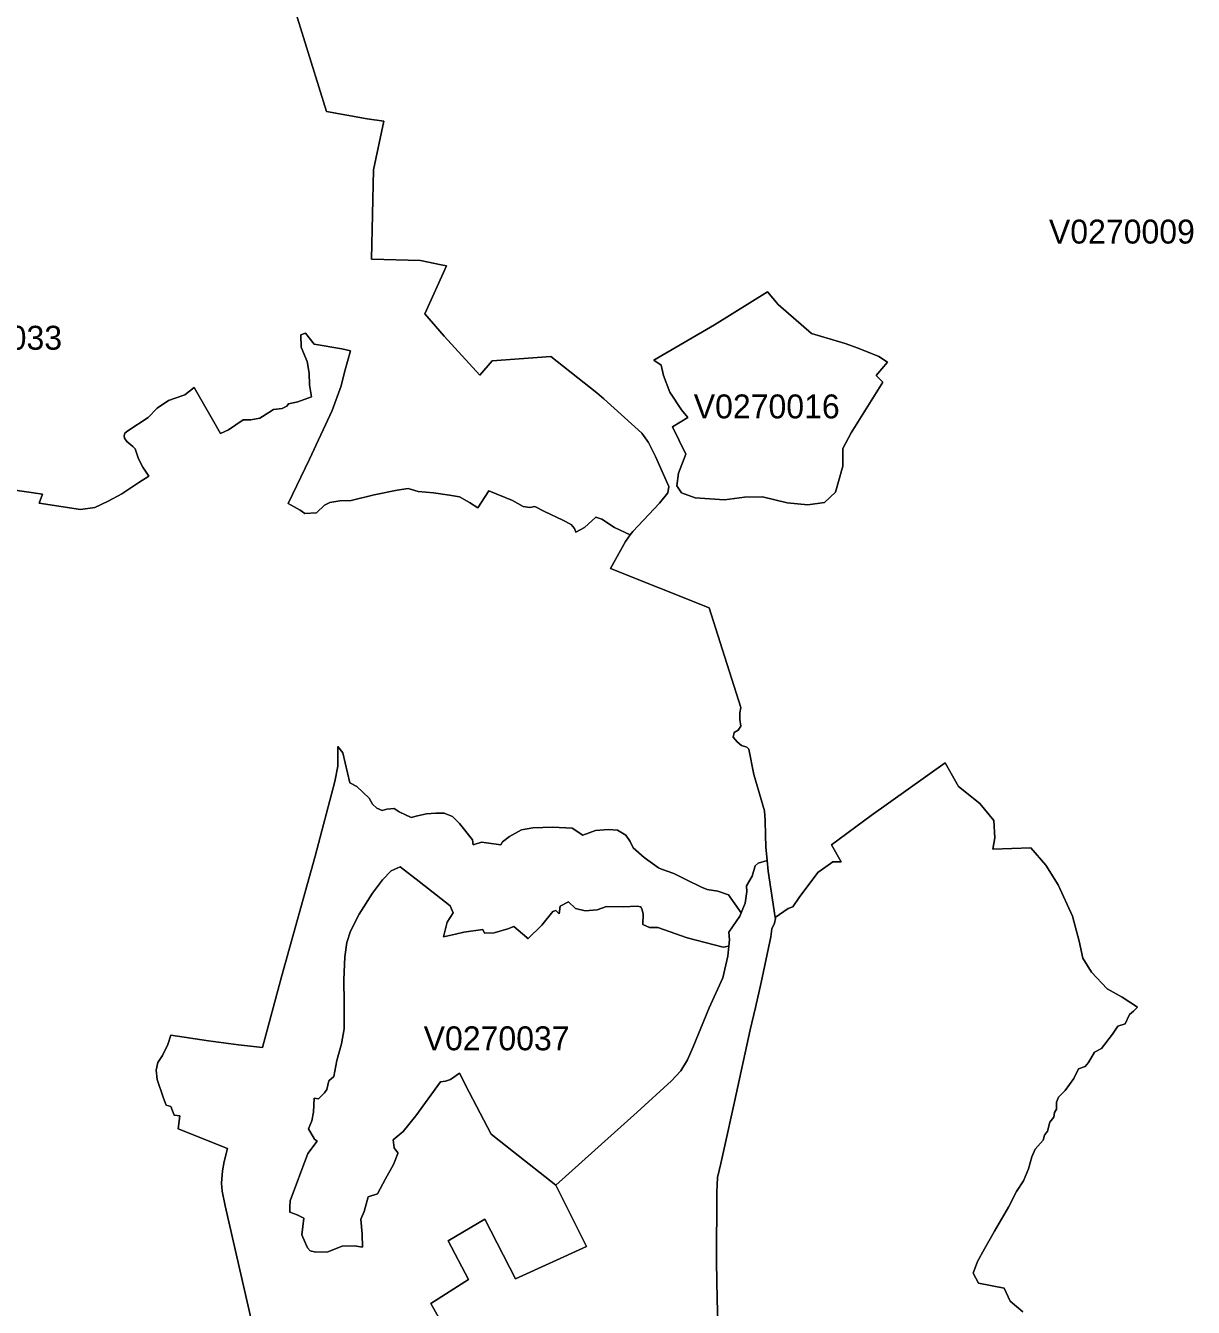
# Model space of a CAD drawing. Extents: x 369010 to 735936, y 6377141 to 6616555.
# Drawn here: x 408735 to 413614, y 6463018 to 6468374 of the extents above; entities that cross this region are included whole.
import ezdxf
from ezdxf.enums import TextEntityAlignment as Align

# ---------------------------------------------------------------- set-up
doc = ezdxf.new("R2010")
doc.units = 0
doc.header["$LTSCALE"] = 40
doc.layers.add('3', color=7, linetype='Continuous', lineweight=13)
doc.layers.add('4', color=7, linetype='Continuous')

msp = doc.modelspace()

# ---------------------------------------------------------------- linework, layer by layer
at = {"layer": '3'}
for points in [[(409863.88, 6468427.37), (409992.14, 6468015.43), (410162.61, 6467984.15), (410231.63, 6467975.04), (410189.26, 6467771.14), (410179.99, 6467397.77), (410385.54, 6467392.8), (410471.11, 6467374.59), (410493.45, 6467371.12), (410403.09, 6467170.2), (410483.52, 6467076.03), (410632.64, 6466913.83), (410684.28, 6466973.25), (410930.05, 6466991.29), (411121.21, 6466839.85), (411151.33, 6466814.53), (411310.21, 6466671.2), (411337.85, 6466632.64), (411367.48, 6466573.56), (411422.76, 6466448.77), (411418.95, 6466421.95), (411383.53, 6466378.76), (411271.65, 6466260.26), (411261.23, 6466246.02), (411241.53, 6466218.88), (411178.97, 6466105.18), (411591.57, 6465941.83), (411636.75, 6465796.68), (411723.64, 6465525.09), (411719.34, 6465502.58), (411719.34, 6465474.77), (411722.82, 6465445.98), (411712.39, 6465429.43), (411695.01, 6465419.5), (411691.37, 6465400.46), (411707.92, 6465381.26), (411726.79, 6465366.04), (411748.8, 6465358.76), (411756.25, 6465350.98), (411777.6, 6465244.56), (411822.78, 6465092.46), (411825.76, 6465052.9), (411826.26, 6464991.67), (411828.41, 6464943.01), (411833.54, 6464885.75), (411837.51, 6464841.06), (411867.47, 6464647.09), (411920.76, 6464685.15), (411941.12, 6464691.11), (411967.27, 6464730.34), (412045.38, 6464835.43), (412108.11, 6464879.46), (412142.87, 6464879.46), (412102.32, 6464951.29), (412268.15, 6465073.1), (412576.82, 6465293.22), (412632.43, 6465194.25), (412721.96, 6465122.91), (412781.05, 6465052.9), (412784.86, 6464979.59), (412777.08, 6464932.58), (412935.46, 6464938.05), (412997.86, 6464865.39), (413049.5, 6464783.63), (413109.57, 6464652.55), (413137.71, 6464547.95), (413152.44, 6464476.95), (413189.18, 6464418.03), (413254.56, 6464349.51), (413316.12, 6464314.43), (413380.17, 6464272.55), (413364.62, 6464255.51), (413346.91, 6464241.77), (413329.86, 6464202.55), (413299.08, 6464193.44), (413275.91, 6464160.01), (413230.72, 6464099.11), (413200.6, 6464084.04), (413175.78, 6464041.51), (413162.7, 6464024.63), (413133.9, 6464014.7), (413115.04, 6463974.15), (413078.96, 6463924.33), (413050.82, 6463895.7), (413042.21, 6463874.68), (413042.88, 6463846.55), (413033.77, 6463832.15), (413031.13, 6463811.96), (413014.08, 6463792.26), (413005.14, 6463754.69), (412991.9, 6463736.98)], [(411367.48, 6466573.56), (411337.85, 6466632.64), (411310.21, 6466671.2), (411151.33, 6466814.53), (411121.21, 6466839.85), (410930.05, 6466991.29), (410684.28, 6466973.25), (410632.64, 6466913.83), (410483.52, 6467076.03), (410403.09, 6467170.2), (410493.45, 6467371.12), (410471.11, 6467374.59), (410385.54, 6467392.8), (410179.99, 6467397.77), (410189.26, 6467771.14), (410231.63, 6467975.04), (410162.61, 6467984.15), (409992.14, 6468015.43), (409863.88, 6468427.37)], [(408672.41, 6466435.86), (408805.64, 6466416.16), (408791.24, 6466378.26), (408964.53, 6466351.95), (409024.77, 6466359.89), (409079.55, 6466387.36), (409136.98, 6466417.32), (409207.65, 6466464.49), (409250.68, 6466491.96), (409224.53, 6466528.54), (409207.49, 6466563.29), (409193.09, 6466605.17), (409182.66, 6466615.59), (409157.84, 6466636.61), (409148.73, 6466649.69), (409147.41, 6466660.11), (409150.06, 6466670.54), (409161.81, 6466680.97), (409246.71, 6466737.24), (409284.61, 6466775.14), (409331.61, 6466807.74), (409360.41, 6466817.01), (409400.96, 6466831.41), (409440.02, 6466861.37), (409549.91, 6466670.38), (409582.52, 6466684.77), (409643.92, 6466726.65), (409676.69, 6466726.65), (409714.43, 6466734.43), (409751, 6466757.93), (409771.52, 6466769.84), (409806.78, 6466773.65), (409826.31, 6466784.24), (409834.25, 6466793.34), (409872.15, 6466802.45), (409929.58, 6466823.47), (409921.8, 6466873.12), (409919.65, 6466922.27), (409911.87, 6466970.27), (409885.89, 6467030.18), (409884.56, 6467082.15), (409904.09, 6467088.6), (409940.5, 6467043.09), (410056.19, 6467023.73), (410092.6, 6467014.62), (410067.94, 6466926.08), (410053.38, 6466869.15), (410015.48, 6466765.87), (409921.47, 6466561.97), (409832.76, 6466376.94), (409882.41, 6466349.46), (409902.11, 6466335.06), (409950.43, 6466337.71), (409984.36, 6466370.32), (410006.54, 6466382.07), (410048.41, 6466388.69), (410095.08, 6466390.01), (410191.74, 6466413.51), (410287.07, 6466433.21), (410334.07, 6466439.66), (410375.94, 6466427.91), (410439.99, 6466421.46), (410506.53, 6466412.19), (410548.07, 6466404.41), (410589.78, 6466380.91), (410625.03, 6466358.73), (410670.87, 6466430.56), (410768.85, 6466390.01), (410814.03, 6466364.03), (410841.51, 6466360.22), (410862.36, 6466365.35), (410902.91, 6466343.17), (410980.03, 6466307.92), (411013.96, 6466289.55), (411028.36, 6466272.5), (411033.49, 6466258.1), (411070.07, 6466276.48), (411117.24, 6466319.67), (411142.89, 6466311.89), (411195.19, 6466276.48), (411261.23, 6466246.02), (411271.65, 6466260.26), (411383.53, 6466378.76), (411418.95, 6466421.95), (411422.76, 6466448.77), (411367.48, 6466573.56)], [(411719.34, 6465474.77), (411719.34, 6465502.58), (411723.64, 6465525.09), (411636.75, 6465796.68), (411591.57, 6465941.83), (411178.97, 6466105.18), (411241.53, 6466218.88), (411261.23, 6466246.02), (411195.19, 6466276.48), (411142.89, 6466311.89), (411117.24, 6466319.67), (411070.07, 6466276.48), (411033.49, 6466258.1), (411028.36, 6466272.5), (411013.96, 6466289.55), (410980.03, 6466307.92), (410902.91, 6466343.17), (410862.36, 6466365.35), (410841.51, 6466360.22), (410814.03, 6466364.03), (410768.85, 6466390.01), (410670.87, 6466430.56), (410625.03, 6466358.73), (410589.78, 6466380.91), (410548.07, 6466404.41), (410506.53, 6466412.19), (410439.99, 6466421.46), (410375.94, 6466427.91), (410334.07, 6466439.66), (410287.07, 6466433.21), (410191.74, 6466413.51), (410095.08, 6466390.01), (410048.41, 6466388.69), (410006.54, 6466382.07), (409984.36, 6466370.32), (409950.43, 6466337.71), (409902.11, 6466335.06), (409882.41, 6466349.46), (409832.76, 6466376.94), (409921.47, 6466561.97), (410015.48, 6466765.87), (410053.38, 6466869.15), (410067.94, 6466926.08), (410092.6, 6467014.62), (410056.19, 6467023.73), (409940.5, 6467043.09), (409904.09, 6467088.6), (409884.56, 6467082.15), (409885.89, 6467030.18), (409911.87, 6466970.27), (409919.65, 6466922.27), (409921.8, 6466873.12), (409929.58, 6466823.47), (409872.15, 6466802.45), (409834.25, 6466793.34), (409826.31, 6466784.24), (409806.78, 6466773.65), (409771.52, 6466769.84), (409751, 6466757.93), (409714.43, 6466734.43), (409676.69, 6466726.65), (409643.92, 6466726.65), (409582.52, 6466684.77), (409549.91, 6466670.38), (409440.02, 6466861.37)], [(409440.02, 6466861.37), (409400.96, 6466831.41), (409360.41, 6466817.01), (409331.61, 6466807.74), (409284.61, 6466775.14), (409246.71, 6466737.24), (409161.81, 6466680.97), (409150.06, 6466670.54), (409147.41, 6466660.11), (409148.73, 6466649.69), (409157.84, 6466636.61), (409182.66, 6466615.59), (409193.09, 6466605.17), (409207.49, 6466563.29), (409224.53, 6466528.54), (409250.68, 6466491.96), (409207.65, 6466464.49), (409136.98, 6466417.32), (409079.55, 6466387.36), (409024.77, 6466359.89), (408964.53, 6466351.95), (408791.24, 6466378.26), (408805.64, 6466416.16), (408672.41, 6466435.86)], [(409725.68, 6462755.71), (409569.11, 6463442.22), (409556.04, 6463503.62), (409553.39, 6463536.39), (409557.36, 6463588.69), (409565.14, 6463627.92), (409578.38, 6463682.04), (409372, 6463764.46), (409379.78, 6463817.75), (409356.27, 6463820.4), (409341.88, 6463856.97), (409322.35, 6463862.27), (409310.6, 6463892.23), (409284.45, 6463970.67), (409280.47, 6464008.74), (409287.09, 6464041.34), (409306.46, 6464069.65), (409329.96, 6464116.65), (409341.71, 6464155.87), (409499.77, 6464131.05), (409625.22, 6464114.17), (409724.52, 6464103.57), (409804.96, 6464398.5), (409944.31, 6464903.62), (410026.73, 6465214.77), (410039.81, 6465280.14), (410039.81, 6465361.24), (410060.66, 6465335.09), (410089.46, 6465209.64), (410119.25, 6465193.91), (410170.22, 6465145.59), (410184.62, 6465120.76), (410202.83, 6465103.71), (410225.01, 6465094.61), (410244.7, 6465099.91), (410274.66, 6465102.39), (410295.68, 6465088.16), (410346.65, 6465064.49), (410372.63, 6465072.43), (410410.54, 6465080.21), (410449.43, 6465083.03), (410483.36, 6465083.03), (410518.61, 6465068.63), (410547.41, 6465039.83), (410602.19, 6464971.81), (410604.84, 6464950.95), (410640.09, 6464961.38), (410660.94, 6464958.73), (410721.02, 6464950.95), (410727.64, 6464962.71), (410757.6, 6464986.21), (410807.25, 6465013.68), (410854.42, 6465021.46), (410937.33, 6465024.44), (411018.27, 6465020.47), (411063.94, 6464991.67), (411116.24, 6465010.04), (411171.19, 6465015.17), (411207.77, 6465011.36), (411243.02, 6464991.67), (411261.23, 6464964.19), (411274.3, 6464938.05), (411319.65, 6464897.99), (411379.73, 6464854.8), (411391.48, 6464848.34), (411443.78, 6464831.29), (411495.91, 6464803.82), (411558.64, 6464773.87), (411582.14, 6464764.6), (411627.98, 6464756.82), (411672.34, 6464742.42), (411725.3, 6464666.62), (411741.52, 6464706.84), (411748.14, 6464755.16), (411746.81, 6464779.99), (411770.32, 6464819.21), (411783.39, 6464862.41), (411796.47, 6464874.16), (411833.54, 6464885.75), (411828.41, 6464943.01), (411826.26, 6464991.67), (411825.76, 6465052.9), (411822.78, 6465092.46), (411777.6, 6465244.56), (411756.25, 6465350.98), (411748.8, 6465358.76), (411726.79, 6465366.04), (411707.92, 6465381.26), (411691.37, 6465400.46), (411695.01, 6465419.5), (411712.39, 6465429.43), (411722.82, 6465445.98), (411719.34, 6465474.77)], [(411315.51, 6464660.66), (411314.19, 6464617.46), (411341.66, 6464605.71), (411376.91, 6464605.71), (411499.72, 6464562.52), (411649.66, 6464523.46), (411673.5, 6464526.93), (411676.14, 6464553.74), (411673.66, 6464585.19), (411719.34, 6464651.89), (411725.3, 6464666.62), (411672.34, 6464742.42), (411627.98, 6464756.82), (411582.14, 6464764.6), (411558.64, 6464773.87), (411495.91, 6464803.82), (411443.78, 6464831.29), (411391.48, 6464848.34), (411379.73, 6464854.8), (411319.65, 6464897.99), (411274.3, 6464938.05), (411261.23, 6464964.19), (411243.02, 6464991.67), (411207.77, 6465011.36), (411171.19, 6465015.17), (411116.24, 6465010.04), (411063.94, 6464991.67), (411018.27, 6465020.47), (410937.33, 6465024.44), (410854.42, 6465021.46), (410807.25, 6465013.68), (410757.6, 6464986.21), (410727.64, 6464962.71), (410721.02, 6464950.95), (410660.94, 6464958.73), (410640.09, 6464961.38), (410604.84, 6464950.95), (410602.19, 6464971.81), (410547.41, 6465039.83), (410518.61, 6465068.63), (410483.36, 6465083.03), (410449.43, 6465083.03), (410410.54, 6465080.21), (410372.63, 6465072.43), (410346.65, 6465064.49), (410295.68, 6465088.16), (410274.66, 6465102.39), (410244.7, 6465099.91), (410225.01, 6465094.61), (410202.83, 6465103.71), (410184.62, 6465120.76), (410170.22, 6465145.59), (410119.25, 6465193.91), (410089.46, 6465209.64), (410060.66, 6465335.09), (410039.81, 6465361.24), (410039.81, 6465280.14), (410026.73, 6465214.77), (409944.31, 6464903.62), (409804.96, 6464398.5), (409724.52, 6464103.57), (409625.22, 6464114.17), (409499.77, 6464131.05), (409341.71, 6464155.87), (409329.96, 6464116.65), (409306.46, 6464069.65), (409287.09, 6464041.34), (409280.47, 6464008.74), (409284.45, 6463970.67), (409310.6, 6463892.23), (409322.35, 6463862.27), (409341.88, 6463856.97), (409356.27, 6463820.4), (409379.78, 6463817.75), (409372, 6463764.46), (409578.38, 6463682.04), (409565.14, 6463627.92), (409557.36, 6463588.69), (409553.39, 6463536.39), (409556.04, 6463503.62), (409569.11, 6463442.22), (409725.68, 6462755.71)], [(412902.03, 6462999.17), (412848.41, 6463043.02), (412823.58, 6463097.31), (412716.34, 6463119.16), (412694.66, 6463160.37), (412712.36, 6463208.86), (412741.16, 6463262.48), (412783.03, 6463335.64), (412842.45, 6463436.26), (412874.89, 6463502.3), (412904.35, 6463546.16), (412925.86, 6463596.47), (412938.94, 6463646.12), (412952.68, 6463678.89), (412986.11, 6463716.13), (412991.9, 6463736.98), (413005.14, 6463754.69), (413014.08, 6463792.26), (413031.13, 6463811.96), (413033.77, 6463832.15), (413042.88, 6463846.55), (413042.21, 6463874.68), (413050.82, 6463895.7), (413078.96, 6463924.33), (413115.04, 6463974.15), (413133.9, 6464014.7), (413162.7, 6464024.63), (413175.78, 6464041.51), (413200.6, 6464084.04), (413230.72, 6464099.11), (413275.91, 6464160.01), (413299.08, 6464193.44), (413329.86, 6464202.55), (413346.91, 6464241.77), (413364.62, 6464255.51), (413380.17, 6464272.55), (413316.12, 6464314.43), (413254.56, 6464349.51), (413189.18, 6464418.03), (413152.44, 6464476.95), (413137.71, 6464547.95), (413109.57, 6464652.55), (413049.5, 6464783.63), (412997.86, 6464865.39), (412935.46, 6464938.05), (412777.08, 6464932.58), (412784.86, 6464979.59), (412781.05, 6465052.9), (412721.96, 6465122.91), (412632.43, 6465194.25), (412576.82, 6465293.22), (412268.15, 6465073.1), (412102.32, 6464951.29), (412142.87, 6464879.46), (412108.11, 6464879.46), (412045.38, 6464835.43), (411967.27, 6464730.34), (411941.12, 6464691.11), (411920.76, 6464685.15), (411867.47, 6464647.09)], [(411635.76, 6462690.5), (411625, 6463051.13), (411621.2, 6463207.54), (411623.84, 6463498.66), (411626, 6463560.56), (411640.4, 6463618.48), (411653.47, 6463681.37), (411697.16, 6463876.01), (411762.04, 6464178.05), (411785.05, 6464270.9), (411808.55, 6464375.33), (411849.26, 6464566.82), (411853.07, 6464600.25), (411863.66, 6464623.42), (411867.96, 6464643.28), (411867.47, 6464647.09), (411837.51, 6464841.06), (411833.54, 6464885.75), (411796.47, 6464874.16), (411783.39, 6464862.41), (411770.32, 6464819.21), (411746.81, 6464779.99), (411748.14, 6464755.16), (411741.52, 6464706.84), (411725.3, 6464666.62), (411719.34, 6464651.89), (411673.66, 6464585.19), (411676.14, 6464553.74), (411673.5, 6464526.93), (411669.69, 6464485.23), (411648.84, 6464395.03), (411591.41, 6464269.57), (411524.87, 6464106.55), (411500.05, 6464051.61), (411472.57, 6464005.93), (411433.35, 6463964.05), (411290.35, 6463834.13), (410951.07, 6463528.78), (411079.34, 6463271.92), (410781.43, 6463137.53), (410653.66, 6463385.95), (410500.73, 6463295.75), (410585.64, 6463133.72), (410427.58, 6463034.25), (410591.1, 6462742.14)], [(410272.67, 6463614.84), (410289.72, 6463660.52), (410289.72, 6463663.17), (410275.32, 6463684.19), (410271.35, 6463718.12), (410313.22, 6463752.04), (410365.02, 6463818.58), (410468.13, 6463959.92), (410488.98, 6463962.4), (410510, 6463970.34), (410547.9, 6463996.49), (410588.29, 6463916.72), (410679.81, 6463741.45), (410773.49, 6463667.47), (410951.07, 6463528.78), (411290.35, 6463834.13), (411433.35, 6463964.05), (411472.57, 6464005.93), (411500.05, 6464051.61), (411524.87, 6464106.55), (411591.41, 6464269.57), (411648.84, 6464395.03), (411669.69, 6464485.23), (411673.5, 6464526.93), (411649.66, 6464523.46), (411499.72, 6464562.52), (411376.91, 6464605.71), (411341.66, 6464605.71), (411314.19, 6464617.46), (411315.51, 6464660.66), (411311.7, 6464678.87), (411305.25, 6464691.94), (411290.85, 6464694.59), (411233.42, 6464691.94), (411161.59, 6464693.26), (411123.69, 6464678.87), (411072.72, 6464674.89), (411032.17, 6464684.16), (411003.54, 6464712.79), (410968.12, 6464694.59), (410964.31, 6464661.82), (410949.91, 6464676.22), (410938.66, 6464672.25), (410891.66, 6464614.82), (410834.23, 6464557.22), (410828.93, 6464563.84), (410775.47, 6464609.52), (410750.65, 6464599.09), (410693.05, 6464583.37), (410652.67, 6464582.05), (410645.22, 6464596.44), (410565.61, 6464586.02), (410531.52, 6464576.75), (410480.54, 6464566.32), (410496.27, 6464627.73), (410521.09, 6464666.95), (410509.34, 6464695.75), (410380.08, 6464797.7), (410300.31, 6464859.27), (410262.41, 6464842.22), (410225.83, 6464804.32), (410184.13, 6464748.05), (410129.18, 6464660.49), (410093.1, 6464590.49), (410077.38, 6464541.99), (410069.43, 6464483.24), (410064.3, 6464386.42), (410065.62, 6464290.1), (410065.62, 6464181.53), (410055.2, 6464118.8), (410035.5, 6464048.79), (410022.43, 6463982.09), (410001.57, 6463963.89), (409993.8, 6463928.64), (409984.53, 6463914.24), (409958.54, 6463889.41), (409940.17, 6463891.89), (409937.52, 6463833.14), (409931.07, 6463796.56), (409917.66, 6463763.13), (409942.49, 6463721.26), (409952.92, 6463712.16), (409913.69, 6463661.18), (409840.54, 6463462.41), (409839.22, 6463437.59), (409839.22, 6463415.24), (409869.34, 6463404.82), (409897.97, 6463390.42), (409888.87, 6463321.24), (409912.37, 6463266.29), (409924.12, 6463254.54), (409947.62, 6463247.92), (409997.27, 6463249.24), (410057.35, 6463274.07), (410109.65, 6463275.39), (410142.25, 6463268.94), (410140.93, 6463323.88), (410135.8, 6463386.61), (410150.2, 6463417.89), (410165.75, 6463479.46)], [(410591.1, 6462742.14), (410427.58, 6463034.25), (410585.64, 6463133.72), (410500.73, 6463295.75), (410653.66, 6463385.95), (410781.43, 6463137.53), (411079.34, 6463271.92), (410951.07, 6463528.78), (410773.49, 6463667.47), (410679.81, 6463741.45), (410588.29, 6463916.72), (410547.9, 6463996.49), (410510, 6463970.34), (410488.98, 6463962.4), (410468.13, 6463959.92), (410365.02, 6463818.58), (410313.22, 6463752.04), (410271.35, 6463718.12), (410275.32, 6463684.19), (410289.72, 6463663.17), (410289.72, 6463660.52), (410272.67, 6463614.84), (410238.74, 6463554.76), (410204.98, 6463492.53), (410165.75, 6463479.46), (410150.2, 6463417.89), (410135.8, 6463386.61), (410140.93, 6463323.88), (410142.25, 6463268.94), (410109.65, 6463275.39), (410057.35, 6463274.07), (409997.27, 6463249.24), (409947.62, 6463247.92), (409924.12, 6463254.54), (409912.37, 6463266.29), (409888.87, 6463321.24), (409897.97, 6463390.42), (409869.34, 6463404.82), (409839.22, 6463415.24), (409839.22, 6463437.59), (409840.54, 6463462.41), (409913.69, 6463661.18), (409952.92, 6463712.16), (409942.49, 6463721.26), (409917.66, 6463763.13), (409931.07, 6463796.56), (409937.52, 6463833.14), (409940.17, 6463891.89), (409958.54, 6463889.41), (409984.53, 6463914.24), (409993.8, 6463928.64), (410001.57, 6463963.89), (410022.43, 6463982.09), (410035.5, 6464048.79), (410055.2, 6464118.8), (410065.62, 6464181.53), (410065.62, 6464290.1), (410064.3, 6464386.42), (410069.43, 6464483.24), (410077.38, 6464541.99), (410093.1, 6464590.49), (410129.18, 6464660.49), (410184.13, 6464748.05), (410225.83, 6464804.32), (410262.41, 6464842.22), (410300.31, 6464859.27), (410380.08, 6464797.7), (410509.34, 6464695.75), (410521.09, 6464666.95), (410496.27, 6464627.73), (410480.54, 6464566.32), (410531.52, 6464576.75), (410565.61, 6464586.02), (410645.22, 6464596.44), (410652.67, 6464582.05), (410693.05, 6464583.37), (410750.65, 6464599.09), (410775.47, 6464609.52), (410828.93, 6464563.84), (410834.23, 6464557.22), (410891.66, 6464614.82), (410938.66, 6464672.25), (410949.91, 6464676.22), (410964.31, 6464661.82), (410968.12, 6464694.59), (411003.54, 6464712.79), (411032.17, 6464684.16), (411072.72, 6464674.89), (411123.69, 6464678.87), (411161.59, 6464693.26), (411233.42, 6464691.94), (411290.85, 6464694.59), (411305.25, 6464691.94), (411311.7, 6464678.87), (411315.51, 6464660.66)], [(411867.47, 6464647.09), (411867.96, 6464643.28), (411863.66, 6464623.42), (411853.07, 6464600.25), (411849.26, 6464566.82), (411808.55, 6464375.33), (411785.05, 6464270.9), (411762.04, 6464178.05), (411697.16, 6463876.01), (411653.47, 6463681.37), (411640.4, 6463618.48), (411626, 6463560.56), (411623.84, 6463498.66), (411621.2, 6463207.54), (411625, 6463051.13), (411635.76, 6462690.5)], [(412991.9, 6463736.98), (412986.11, 6463716.13), (412952.68, 6463678.89), (412938.94, 6463646.12), (412925.86, 6463596.47), (412904.35, 6463546.16), (412874.89, 6463502.3), (412842.45, 6463436.26), (412783.03, 6463335.64), (412741.16, 6463262.48), (412712.36, 6463208.86), (412694.66, 6463160.37), (412716.34, 6463119.16), (412823.58, 6463097.31), (412848.41, 6463043.02), (412902.03, 6462999.17)], [(410165.75, 6463479.46), (410204.98, 6463492.53), (410238.74, 6463554.76), (410272.67, 6463614.84)]]:
    msp.add_lwpolyline(points, dxfattribs=at)
for points in [[(412019.4, 6467087.94), (412159.42, 6467045.9), (412214.03, 6467027.04), (412299.43, 6466991.78), (412335.84, 6466968.45), (412289.01, 6466911.68), (412317.14, 6466884.37), (412185.07, 6466671.86), (412149.15, 6466606.99), (412149.65, 6466533.83), (412119.03, 6466424.77), (412073.19, 6466381.07), (412004.01, 6466371.64), (411916.62, 6466380.58), (411813.84, 6466405.4), (411738.87, 6466403.25), (411655.79, 6466392), (411532.32, 6466400.44), (411476.05, 6466422.12), (411456.52, 6466450.92), (411462.48, 6466503.71), (411493.1, 6466583.49), (411438.65, 6466698.01), (411501.37, 6466736.58), (411475.06, 6466768.68), (411426.9, 6466842.5), (411400.75, 6466912.18), (411390.98, 6466955.7), (411360.53, 6466975.9), (411612.92, 6467124.35), (411834.7, 6467261.56), (411879.22, 6467209.26)], [(412019.4, 6467087.94), (411879.22, 6467209.26), (411834.7, 6467261.56), (411612.92, 6467124.35), (411360.53, 6466975.9), (411390.98, 6466955.7), (411400.75, 6466912.18), (411426.9, 6466842.5), (411475.06, 6466768.68), (411501.37, 6466736.58), (411438.65, 6466698.01), (411493.1, 6466583.49), (411462.48, 6466503.71), (411456.52, 6466450.92), (411476.05, 6466422.12), (411532.32, 6466400.44), (411655.79, 6466392), (411738.87, 6466403.25), (411813.84, 6466405.4), (411916.62, 6466380.58), (412004.01, 6466371.64), (412073.19, 6466381.07), (412119.03, 6466424.77), (412149.65, 6466533.83), (412149.15, 6466606.99), (412185.07, 6466671.86), (412317.14, 6466884.37), (412289.01, 6466911.68), (412335.84, 6466968.45), (412299.43, 6466991.78), (412214.03, 6467027.04), (412159.42, 6467045.9)]]:
    msp.add_lwpolyline(points, close=True, dxfattribs=at)

# ---------------------------------------------------------------- texts
at = {"layer": '4'}
for s, p in [('V0270009', (413315.69, 6467463.54)), ('V0270033', (408582.61, 6467019.84)), ('V0270016', (411831.68, 6466732.9)), ('V0270037', (410703.12, 6464092.06))]:
    msp.add_text(s, height=100, dxfattribs=at).set_placement(p, align=Align.CENTER)

doc.saveas('drawing.dxf')
